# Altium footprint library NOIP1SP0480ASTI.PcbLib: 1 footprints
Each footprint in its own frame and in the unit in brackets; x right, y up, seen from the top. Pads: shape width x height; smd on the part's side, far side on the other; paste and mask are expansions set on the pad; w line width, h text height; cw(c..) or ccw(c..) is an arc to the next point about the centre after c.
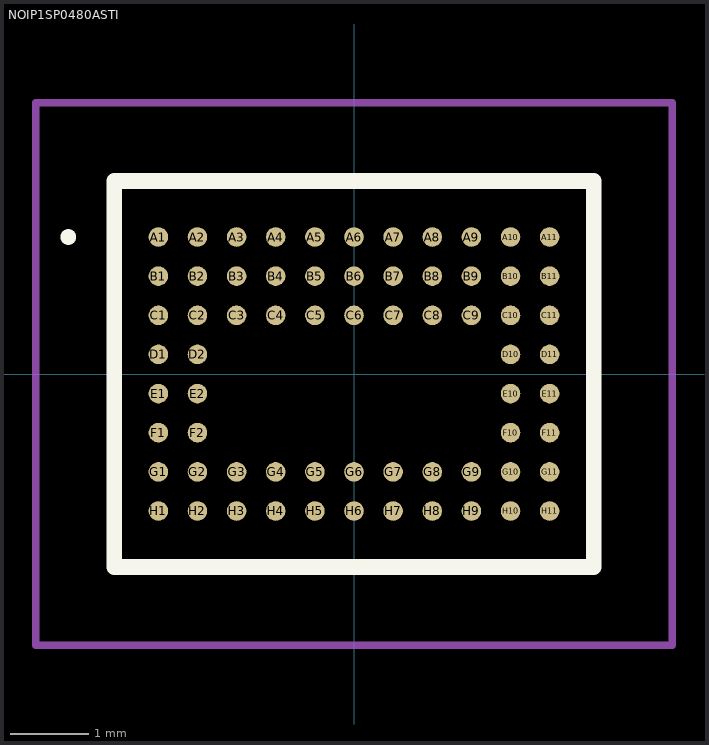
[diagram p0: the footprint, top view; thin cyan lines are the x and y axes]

## NOIP1SP0480ASTI [mm]
pads (67):
  round 0.25 smd: A1(-2.5,1.75) A2(-2,1.75) A3(-1.5,1.75) A4(-1,1.75) A5(-0.5,1.75) A6(0,1.75) A7(0.5,1.75) A8(1,1.75) A9(1.5,1.75) A10(2,1.75) A11(2.5,1.75) B1(-2.5,1.25) B2(-2,1.25) B3(-1.5,1.25) B4(-1,1.25) B5(-0.5,1.25) B6(0,1.25) B7(0.5,1.25) B8(1,1.25) B9(1.5,1.25) B10(2,1.25) B11(2.5,1.25) C1(-2.5,0.75) C2(-2,0.75) C3(-1.5,0.75) C4(-1,0.75) C5(-0.5,0.75) C6(0,0.75) C7(0.5,0.75) C8(1,0.75) C9(1.5,0.75) C10(2,0.75) C11(2.5,0.75) D1(-2.5,0.25) D2(-2,0.25) D10(2,0.25) D11(2.5,0.25) E1(-2.5,-0.25) E2(-2,-0.25) E10(2,-0.25) E11(2.5,-0.25) F1(-2.5,-0.75) F2(-2,-0.75) F10(2,-0.75) F11(2.5,-0.75) G1(-2.5,-1.25) G2(-2,-1.25) G3(-1.5,-1.25) G4(-1,-1.25) G5(-0.5,-1.25) G6(0,-1.25) G7(0.5,-1.25) G8(1,-1.25) G9(1.5,-1.25) G10(2,-1.25) G11(2.5,-1.25) H1(-2.5,-1.75) H2(-2,-1.75) H3(-1.5,-1.75) H4(-1,-1.75) H5(-0.5,-1.75) H6(0,-1.75) H7(0.5,-1.75) H8(1,-1.75) H9(1.5,-1.75) H10(2,-1.75) H11(2.5,-1.75)
Top Overlay:
  lines w0.1: -3.7,1.75 cw(c-3.65,1.75) -3.6,1.75 ; -3.7,1.75 -3.7,1.75 ; -3.7,1.75 ccw(c-3.65,1.75) -3.6,1.75 ; -3.6,1.75 -3.6,1.75
  lines w0.2: -3.065,-2.465 3.065,-2.465 3.065,2.465 -3.065,2.465 -3.065,-2.465
Mechanical 15:
  lines w0.1: -3.065,-2.465 3.065,-2.465 3.065,2.465 -3.065,2.465 -3.065,-2.465
Mechanical 20:
  lines w0.1: -4.065,-3.465 4.065,-3.465 4.065,3.465 -4.065,3.465 -4.065,-3.465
